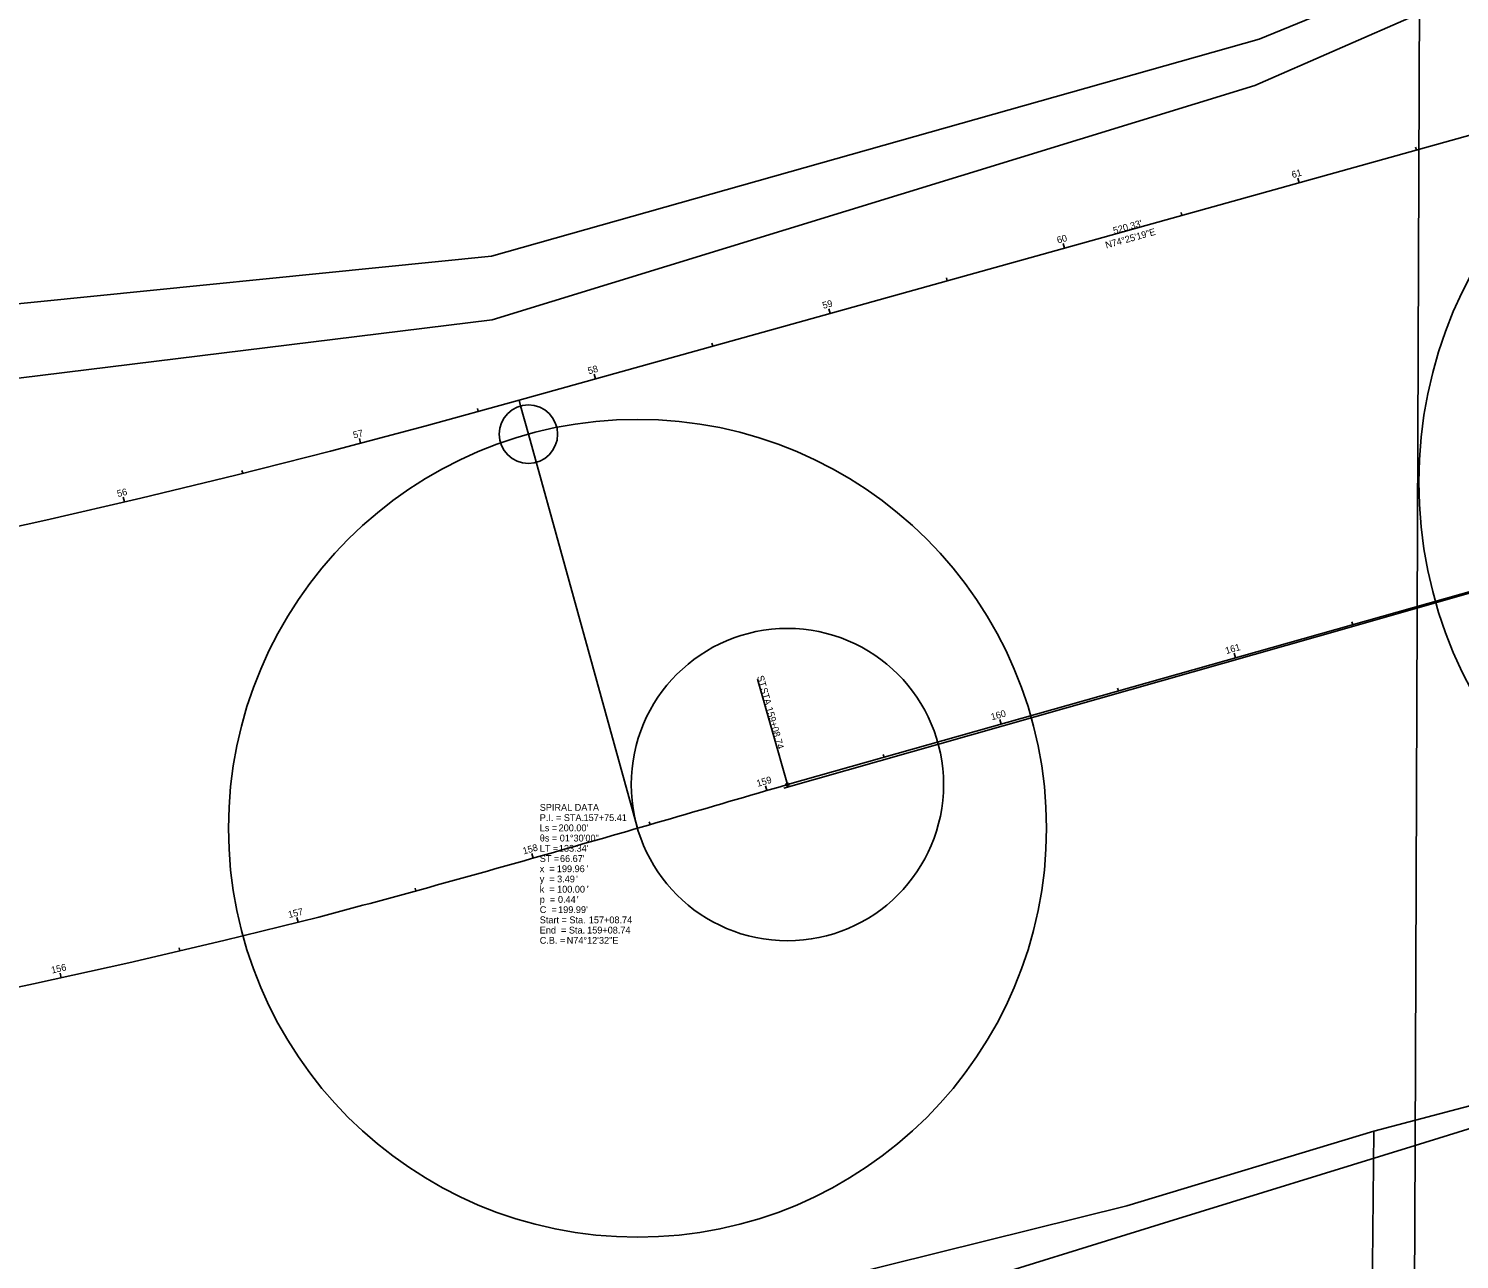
# Model space of a CAD drawing. Extents: x 2272920 to 2277360, y 743591 to 745058.
# Drawn here: x 2275610 to 2276197, y 743999 to 744504 of the extents above; entities that cross this region are included whole.
import ezdxf

# ---------------------------------------------------------------- set-up
doc = ezdxf.new("R2010")
doc.units = 0
for name, color, linetype in [('GE_X_Alignment', 7, 'Continuous'), ('GE_X_Alignment_100_Bearings', 7, 'Continuous'), ('GE_X_Alignment_100_Cardinal_Points', 7, 'Continuous'), ('GE_X_Alignment_100_Curve_Data', 7, 'Continuous'), ('GE_X_Alignment_100_Distances', 7, 'Continuous'), ('GE_X_Alignment_100_Stations', 7, 'Continuous'), ('SC_Scratch1', 7, 'Continuous'), ('SC_Scratch2', 7, 'Continuous'), ('SC_Scratch3', 7, 'Continuous')]:
    doc.layers.add(name, color=color, linetype=linetype)

msp = doc.modelspace()

# ---------------------------------------------------------------- linework, layer by layer
at = {"layer": 'GE_X_Alignment'}
for p, q in [((2275811.23, 744351.63), (2276312.44, 744491.37)), ((2275921.44, 744193.73), (2276682.83, 744409.06))]:
    msp.add_line(p, q, dxfattribs=at)
for points in [[(2274981.85, 744214.31), (2275021.89, 744216.67), (2275061.91, 744219.46), (2275101.89, 744222.67), (2275141.84, 744226.3), (2275181.75, 744230.35), (2275221.61, 744234.81), (2275261.43, 744239.7), (2275301.19, 744245), (2275340.89, 744250.72), (2275380.53, 744256.86), (2275420.11, 744263.41), (2275459.61, 744270.38), (2275499.04, 744277.76), (2275538.39, 744285.56), (2275577.65, 744293.77), (2275616.83, 744302.39), (2275655.91, 744311.42), (2275694.9, 744320.86), (2275733.78, 744330.71), (2275772.56, 744340.97), (2275811.23, 744351.63)], [(2275015.98, 744030.43), (2275056.03, 744032.92), (2275096.06, 744035.84), (2275136.05, 744039.18), (2275176, 744042.93), (2275215.91, 744047.11), (2275255.78, 744051.7), (2275295.6, 744056.72), (2275335.36, 744062.15), (2275375.06, 744068), (2275414.7, 744074.27), (2275454.27, 744080.95), (2275493.77, 744088.05), (2275533.19, 744095.56), (2275572.53, 744103.48), (2275611.78, 744111.82), (2275650.95, 744120.57), (2275690.02, 744129.73), (2275728.99, 744139.31)]]:
    msp.add_lwpolyline(points, dxfattribs=at)
msp.add_open_spline([(2275728.99, 744139.31), (2275745.1, 744143.56), (2275777.28, 744152.26), (2275825.4, 744165.85), (2275873.45, 744179.68), (2275905.44, 744189.06), (2275921.44, 744193.73)], degree=3, dxfattribs=at)
at = {"layer": 'GE_X_Alignment_100_Cardinal_Points'}
msp.add_line((2275921.44, 744193.73), (2275909.19, 744237.03), dxfattribs=at)
msp.add_circle((2275921.44, 744193.73), 0.6, dxfattribs=at)
at = {"layer": 'GE_X_Alignment_100_Stations'}
for p, q in [((2276179.76, 744454.38), (2276179.44, 744455.53)), ((2276131.6, 744440.95), (2276131.06, 744442.87)), ((2276083.44, 744427.52), (2276083.11, 744428.68)), ((2276035.27, 744414.09), (2276034.74, 744416.02)), ((2275987.11, 744400.67), (2275986.79, 744401.82)), ((2275938.95, 744387.24), (2275938.41, 744389.16)), ((2275890.78, 744373.81), (2275890.46, 744374.97)), ((2275842.62, 744360.38), (2275842.08, 744362.31)), ((2275794.44, 744347), (2275794.12, 744348.16)), ((2275746.17, 744333.99), (2275745.66, 744335.92)), ((2275697.73, 744321.58), (2275697.44, 744322.74)), ((2275649.13, 744309.85), (2275648.68, 744311.8)), ((2276153.59, 744259.38), (2276153.26, 744260.54)), ((2276105.47, 744245.78), (2276104.93, 744247.7)), ((2276057.36, 744232.17), (2276057.03, 744233.33)), ((2276009.25, 744218.56), (2276008.7, 744220.49)), ((2275961.13, 744204.96), (2275960.81, 744206.11)), ((2275913.04, 744191.28), (2275912.48, 744193.2)), ((2275865.04, 744177.29), (2275864.7, 744178.45)), ((2275816.98, 744163.5), (2275816.43, 744165.42)), ((2275768.82, 744150.04), (2275768.51, 744151.2)), ((2275720.5, 744137.22), (2275720.02, 744139.16)), ((2275671.9, 744125.49), (2275671.62, 744126.65)), ((2275623.15, 744114.36), (2275622.71, 744116.31))]:
    msp.add_line(p, q, dxfattribs=at)
msp.add_open_spline([(2275728.99, 744139.31), (2275745.1, 744143.56), (2275777.28, 744152.26), (2275825.4, 744165.85), (2275873.45, 744179.68), (2275905.44, 744189.06), (2275921.44, 744193.73)], degree=3, dxfattribs=at)
at = {"layer": 'SC_Scratch1'}
for p, q in [((2276183.11, 745028.06), (2276179.2, 744045.49)), ((2276183.11, 745028.06), (2276179.2, 744045.49)), ((2276181.05, 744510.49), (2276113.37, 744480.89)), ((2276113.37, 744480.89), (2275800.25, 744384.65)), ((2275800.25, 744384.65), (2275591, 744358.88)), ((2276152.08, 744258.3), (2276541.02, 744368.96)), ((2276152.08, 744258.3), (2275920.03, 744192.27)), ((2276179.2, 744045.49), (2276364.75, 744102.66)), ((2276078.05, 744014.33), (2276179.21, 744045.49)), ((2276179.21, 744045.5), (2276178.61, 743894.87)), ((2276178.61, 743894.87), (2276179.21, 744045.5)), ((2275727.62, 743905.62), (2276078.05, 744014.33))]:
    msp.add_line(p, q, dxfattribs=at)
for points in [[(2274981.85, 744214.31), (2275021.89, 744216.67), (2275061.91, 744219.46), (2275101.89, 744222.67), (2275141.84, 744226.3), (2275181.75, 744230.35), (2275221.61, 744234.81), (2275261.43, 744239.7), (2275301.19, 744245), (2275340.89, 744250.72), (2275380.53, 744256.86), (2275420.11, 744263.41), (2275459.61, 744270.38), (2275499.04, 744277.76), (2275538.39, 744285.56), (2275577.65, 744293.77), (2275616.83, 744302.39), (2275655.91, 744311.42), (2275694.9, 744320.86), (2275733.78, 744330.71), (2275772.56, 744340.97), (2275811.23, 744351.63)], [(2275015.98, 744030.43), (2275056.03, 744032.92), (2275096.06, 744035.84), (2275136.05, 744039.18), (2275176, 744042.93), (2275215.91, 744047.11), (2275255.78, 744051.7), (2275295.6, 744056.72), (2275335.36, 744062.15), (2275375.06, 744068), (2275414.7, 744074.27), (2275454.27, 744080.95), (2275493.77, 744088.05), (2275533.19, 744095.56), (2275572.53, 744103.48), (2275611.78, 744111.82), (2275650.95, 744120.57), (2275690.02, 744129.73), (2275728.99, 744139.31)]]:
    msp.add_lwpolyline(points, dxfattribs=at)
at = {"layer": 'SC_Scratch2'}
for points in [[(2274851.36, 744274.32), (2275126.05, 744285.07), (2275199.48, 744292.66), (2275297.13, 744305.01), (2275386.2, 744369.23), (2275590.16, 744389.71), (2275799.94, 744410.77), (2276115.15, 744499.95), (2276183.48, 744528.02), (2276197.17, 745045.41), (2275607.93, 745057.52), (2275590.16, 744389.71)], [(2276261.27, 743885.65), (2276214.24, 743898.93), (2276165.44, 743901.53), (2276160.8, 743900.74), (2276162.21, 744051.36), (2276363, 744104.29), (2276412.75, 744129.78), (2276424.87, 744054.26), (2276449.34, 744019.29), (2276611.66, 743886.24), (2276491.44, 743858.39), (2276443.53, 743852.18), (2276388.72, 743850.78), (2276337.7, 743858.82)], [(2276160.8, 743900.74), (2276117.26, 743893.3), (2276072.07, 743874.65), (2276031.68, 743846.31), (2275750.53, 743599.11), (2275702.95, 743693.25), (2275355.81, 743739.96), (2275005.85, 743758.81), (2276060.88, 744020.73), (2276162.21, 744051.36)]]:
    msp.add_lwpolyline(points, dxfattribs=at)
at = {"layer": 'SC_Scratch3'}
msp.add_line((2275859.87, 744175.79), (2275815.07, 744337.65), dxfattribs=at)
msp.add_lwpolyline([(2275815.07, 744337.65), (2275811.89, 744349.23), (2275811.23, 744351.63)], dxfattribs=at)
for centre, radius in [((2276360.77, 744317.98), 180), ((2275815.07, 744337.65), 12), ((2275859.87, 744175.79), 167.95), ((2275921.44, 744193.73), 64.13)]:
    msp.add_circle(centre, radius, dxfattribs=at)

# ---------------------------------------------------------------- texts
at = {"layer": 'GE_X_Alignment_100_Bearings'}
msp.add_text('N74°25\'19"E', height=2.8, rotation=15.57807, dxfattribs=at).set_placement((2276052.42, 744413.89))
at = {"layer": 'GE_X_Alignment_100_Cardinal_Points'}
for s, p in [('ST', (2275908.92, 744238.1)), (' STA. ', (2275910.04, 744234.15)), ('159+08.74', (2275912.58, 744225.18))]:
    msp.add_text(s, height=2.8, rotation=285.79111, dxfattribs=at).set_placement(p)
at = {"layer": 'GE_X_Alignment_100_Curve_Data'}
for s, p in [('SPIRAL DATA', (2275819.73, 744182.95)), ('P.I. = STA. ', (2275819.73, 744178.75)), ('157+75.41', (2275837.72, 744178.75)), ('Ls = ', (2275819.73, 744174.55)), ("200.00'", (2275827.47, 744174.55)), ('θs = ', (2275819.73, 744170.35)), ('LT = ', (2275819.73, 744166.15)), ("133.34'", (2275827.58, 744166.15)), ('01°30\'00"', (2275827.94, 744170.35)), ('ST = ', (2275819.73, 744161.95)), ("66.67'", (2275828.03, 744161.95)), ('x  = ', (2275819.73, 744157.75)), ('3.49', (2275826.86, 744153.55)), ('199.96', (2275826.76, 744157.75)), ("'", (2275834.64, 744153.55)), ("'", (2275839.01, 744157.75)), ('y  = ', (2275819.73, 744153.55)), ('k  = ', (2275819.73, 744149.35)), ('100.00', (2275826.86, 744149.35)), ("'", (2275839.11, 744149.35)), ('p  = ', (2275819.73, 744145.15)), ('0.44', (2275827.21, 744145.15)), ("'", (2275834.99, 744145.15)), ('Start = Sta. ', (2275819.73, 744136.75)), ('C  = ', (2275819.73, 744140.95)), ("199.99'", (2275827.28, 744140.95)), ('157+08.74', (2275839.88, 744136.75)), ('End  = Sta. ', (2275819.73, 744132.55)), ('159+08.74', (2275839.19, 744132.55)), ('C.B. = ', (2275819.73, 744128.35)), ('N74°12\'32"E', (2275830.8, 744128.35))]:
    msp.add_text(s, height=2.8, dxfattribs=at).set_placement(p)
at = {"layer": 'GE_X_Alignment_100_Distances'}
msp.add_text("520.33'", height=2.8, rotation=15.57807, dxfattribs=at).set_placement((2276055.63, 744419.81))
at = {"layer": 'GE_X_Alignment_100_Stations'}
for s, rotation, p in [('61', 15.57807, (2276128.9, 744442.79)), ('60', 15.57807, (2276032.53, 744415.92)), ('59', 15.57807, (2275936.24, 744389.08)), ('58', 15.57807, (2275839.89, 744362.22)), ('57', 14.81682, (2275743.47, 744335.86)), ('56', 13.01173, (2275646.48, 744311.8)), ('161', 15.79111, (2276101.69, 744247.31)), ('160', 15.79111, (2276005.42, 744220.08)), ('159', 16.28824, (2275909.24, 744192.77)), ('158', 15.84766, (2275813.17, 744165.01)), ('157', 13.79881, (2275716.75, 744138.88)), ('156', 12.59489, (2275619.43, 744116.09))]:
    msp.add_text(s, height=2.8, rotation=rotation, dxfattribs=at).set_placement(p)

doc.saveas('drawing.dxf')
